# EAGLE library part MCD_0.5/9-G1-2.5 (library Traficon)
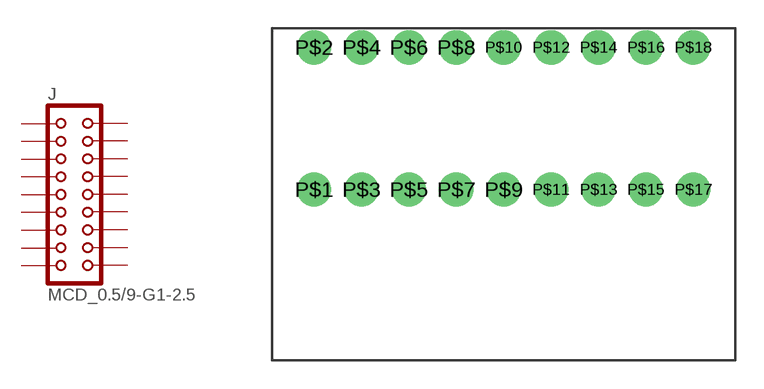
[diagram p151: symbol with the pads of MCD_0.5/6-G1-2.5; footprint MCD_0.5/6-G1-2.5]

Designator prefix J

## MCD_0.5/9-G1-2.5  [MCD_0.5/6-G1-2.5]
P$1  P$1  pas
P$2  P$2  pas
P$3  P$3  pas
P$4  P$4  pas
P$5  P$5  pas
P$6  P$6  pas
P$7  P$7  pas
P$8  P$8  pas
P$9  P$9  pas
P$10  P$10  pas
P$11  P$11  pas
P$12  P$12  pas
P$13  P$13  pas
P$14  P$14  pas
P$15  P$15  pas
P$16  P$16  pas
P$17  P$17  pas
P$18  P$18  pas

## Footprint MCD_0.5/6-G1-2.5 (pad centres in mm)
drill 1.2 round: P$1 -10.5,1.38; P$2 -10.5,8.88; P$3 -8,1.38; P$4 -8,8.88; P$5 -5.5,1.38; P$6 -5.5,8.88; P$7 -3,1.38; P$8 -3,8.88; P$9 -0.5,1.38; P$10 -0.5,8.88; P$11 2,1.38; P$12 2,8.88; P$13 4.5,1.38; P$14 4.5,8.88; P$15 7,1.38; P$16 7,8.88; P$17 9.5,1.38; P$18 9.5,8.88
